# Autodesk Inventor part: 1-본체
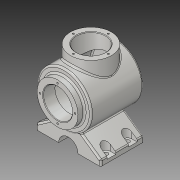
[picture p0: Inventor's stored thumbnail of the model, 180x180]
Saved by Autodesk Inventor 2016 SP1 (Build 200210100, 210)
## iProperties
Created: 2017-04
Part Number: 1-본체
Material: 알루미늄 6061
Document SubType Name: Modeling
Designer: H
Mass: 1664.52 g
Surface Area: 1066.88 cm^2
Volume: 616.49 cm^3
Density: 2.7 g/cm^3
Appearance: 알루미늄 - 평지
Author: H
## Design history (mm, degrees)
sketch "스케치1"
  geometry: L1 (0, 50)-(50, 50); L2 (50, 50)-(50, -46.336); L3 (50, -46.336)-(0, -46.336); L4 (0, -46.336)-(0, 50); L5 (0, 50)-(38, 50); L6 (38, 50)-(38, 62); L7 (38, 62)-(0, 62); L8 (0, 62)-(0, 50); L9 (0, -46.336)-(0, -58); A1 r 113 centre (0, 55) between (50, -46.336) and (0, -58); 1 further point
  constraints: 18 end point, 4 parallel, 2 horizontal, 2 perpendicular, 2 point on circle, 2 point on line, 1 centre point, 1 vertical
  dimensions: "d0" = 108 distance edge to line of A1 L1; "d1" = 100 diameter of L2 L4; "d2" = 12 distance of L5.end L6.end; "d3" = 76 diameter of L6 L4; "d5" = 113 radius of A1; "d6" = 50 distance from line of L1 point (0, 0)
revolve "회전1" sketch "스케치1" stored, may be unused: angle "d7" = 90 deg
sketch "스케치2"
  geometry: C1 r 38 at (0, 0); 1 further point
  constraints: 1 centre point, 1 coincident
  dimensions: "d9" = 76 diameter of C1
extrude "돌출1" join sketch "스케치2" distance "d10" = 65; taper "d11" = 0 deg
sketch "스케치4"
  geometry: L1 (-60, -82)-(60, -82); L2 (60, -82)-(60, -72); L3 (60, -72)-(-60, -72); L4 (-60, -72)-(-60, -82); L5 (-60, -72)-(-21.584, -45.101); L6 (60, -72)-(21.584, -45.101); C1 r 18 at (0, -82); A1 r 50 centre (0, 0) between (-21.584, -45.101) and (21.584, -45.101) reference; 3 further points
  constraints: 12 end point, 2 midpoint, 2 parallel, 2 point on circle, 1 centre point, 1 coincident, 1 equal length, 1 horizontal, 1 perpendicular, 1 vertical alignment
  dimensions: "d33" = 120 distance of L2.end L3.end; "d34" = 10 distance of L1.end L2.end; "d35" = 82 distance from line of point (0, 0) L1; "d36" = 55 deg angle of L5 L4; "d38" = 18 radius of C1
extrude "돌출2" join sketch "스케치4" distance "d39" = 42; taper "d40" = 0 deg; dims "d90" = 38, "d91" = 0
extrude "돌출3" cut sketch "스케치4" stored distance "d41" = 80; taper "d42" = 0 deg
sketch "스케치3"
  geometry: L1 (50, 50)-(50, -46.336) reference; L2 (-50, 50)-(50, 50) reference; L3 (-50, 50)-(-50, -46.336) reference; L4 (40, -39.916)-(40, 40); L5 (40, 40)-(-40, 40); L6 (-40, 40)-(-40, -39.916); L7 (0, 40)-(0, -48); A1 r 113 centre (0, 55) between (-50, -46.336) and (50, -46.336) reference; A2 r 103 centre (0, 55) between (-40, -39.916) and (40, -39.916); 1 further point
  constraints: 8 end point, 3 point on circle, 1 centre point, 1 midpoint, 1 parallel, 1 vertical, 1 other
  dimensions: "d12" = 10 radial gap between concentric circles of A1 A2; "d13" = 10 distance between parallel lines of L1 L4
revolve "회전2" sketch "스케치3" stored, may be unused: angle "d14" = 90 deg
fillet "모깎기1" dims "d8" = 3
hole "구멍1" diameter "d17" = 54; stored, may be unused: countersink angle "d21" = 90 deg, drill point angle "d23" = 118 deg; dims "d15" = 10, "d16" = 10, "d18" = 6, "d19" = 4, "d20" = 2, "d22" = 8
hole "구멍2" diameter "d26" = 54; stored, may be unused: countersink angle "d30" = 90 deg, drill point angle "d32" = 118 deg; dims "d24" = 10, "d25" = 10, "d27" = 6, "d28" = 4, "d29" = 2, "d31" = 8
sketch "스케치5"
  geometry: 2 further points
  constraints: 1 vertical alignment
  dimensions: "d44" = 32.5 distance of point (0, 32.5) point (0, 0)
hole "구멍3" sketch "스케치5" at (0, 32.5) diameter "d45" = 3.242; stored, may be unused: countersink angle "d49" = 90 deg, drill point angle "d51" = 118 deg; dims "d46" = 8, "d47" = 4, "d48" = 2, "d50" = 10
sketch "스케치6"
  geometry: 2 further points
  constraints: 1 vertical alignment
  dimensions: "d55" = 32.5 distance of point (0, 32.5) point (0, 0)
hole "구멍4" sketch "스케치6" at (0, 32.5) diameter "d56" = 3.242; stored, may be unused: countersink angle "d60" = 90 deg, drill point angle "d62" = 118 deg; dims "d57" = 8, "d58" = 4, "d59" = 2, "d61" = 10
chamfer "모따기1" distance "d66" = 1; stored, may be unused: second distance "d67" = 2, angle "d68" = 45 deg
fillet "모깎기2" dims "d69" = 3
fillet "모깎기3" dims "d70" = 3
node "작업 평면2"
sketch "스케치7"
  geometry: 2 further points
  constraints: 1 coincident, 1 other
feature "엠보싱1" sketch "스케치7" dims "d0" = 108, "d1" = 100, "d2" = 12, "d3" = 76, "d5" = 113, "d6" = 50, "d71" = 0.5, "d72" = 0
node "작업 평면1"
sketch "스케치8" dims "d92" = 8
  geometry: L1 (-110, 60)-(-10, 60); L2 (-10, 60)-(-10, 20); L3 (-10, 20)-(-110, 20); L4 (-110, 20)-(-110, 60); L5 (-110, 60)-(-10, 20); L6 (-10, 60)-(-110, 20); L7 (-10, 28)-(0, 28); L8 (0, 28)-(0, 12); L9 (0, 12)-(-10, 12); L10 (-10, 12)-(-10, 28); L11 (0, 77)-(0, 3) reference; 5 further points
  constraints: 20 end point, 4 midpoint, 4 parallel, 2 horizontal, 2 perpendicular, 2 vertical alignment, 1 coincident, 1 collinear, 1 horizontal alignment, 2 other
  dimensions: "d73" = 100 distance of L2.end L3.end; "d74" = 40 distance of L3.end L1.start
extrude "돌출4" cut sketch "스케치8" stored distance "d75" = 80; taper "d76" = 0 deg
hole "구멍5" diameter "d83" = 8; stored, may be unused: countersink angle "d87" = 90 deg, drill point angle "d89" = 118 deg; dims "d81" = 10, "d82" = 10, "d84" = 8, "d85" = 4, "d86" = 2, "d88" = 10
node "솔리드1"
pattern_circular "원형 패턴1" dims angle "d53" = 360 deg
pattern_circular "원형 패턴2" dims angle "d64" = 360 deg
pattern_linear "직사각형 패턴1"
mirror "대칭1"
other parameters: "d43" = -6
